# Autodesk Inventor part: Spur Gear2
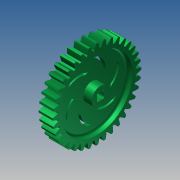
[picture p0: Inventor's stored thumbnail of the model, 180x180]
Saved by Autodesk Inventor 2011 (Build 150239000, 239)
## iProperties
Created: 2010-06
Part Number: Spur Gear2
Material: Steel
Document SubType Name: Modeling
Designer: Phil
Categories: <?xml version="1.0" encoding="UTF-16"?> <MemberInstance><Categories><FamilyTemplate><FamilyTemplateParameter ValueType="xs:double" Id="1" ObjectReferenceKey="da
Density: 1 g/cm^3
CustomPartVersion: 1
Author: Phil
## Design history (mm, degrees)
sketch "Sketch1"
  geometry: C1 r 19.897 at (0, 0)
  constraints: 1 centre point
  dimensions: "d0" = 39.79333 diameter of C1 (= da_da)
extrude "Extrusion1" new body sketch "Sketch1" distance "d1" = 6.35 (= da_b); taper "d2" = 0 deg
sketch "Sketch2"
  geometry: C1 r 19.897 at (0, 0) reference; C2 r 19.05 at (0, 0)
  constraints: 1 centre point, 1 coincident
  dimensions: "d3" = 38.1 diameter of C2 (= da_dw)
feature "Pitch Diameter" sketch "Sketch2" dims "d4" = 76.2, "d5" = 0
workplane "Work Plane1"
workplane "Work Plane2"
workplane "Work Plane3"
feature "Spur Gear" dims "da_b" = 6.35, "da_d" = 38.1, "da_aw" = 25.4, "da_da" = 39.79333, "da_df" = 35.03083, "da_dw" = 38.1, angle "da_beta" = 0 deg, "da_lefttooth" = 0, "da_righttooth" = 0
sketch "Sketch3"
  geometry: C1 r 15.926 at (0, 0); A1 r 19.897 centre (0, 0) between (-3.027, 19.665) and (-3.882, 19.514) reference
  constraints: 1 centre point, 1 coincident
  dimensions: "d20" = 31.8516 diameter of C1
extrude "Extrusion2" cut sketch "Sketch3" distance "d21" = 2.1844; taper "d22" = 0 deg
fillet "Fillet1" dims "d23" = 0.9906
workplane "Work Plane4"
mirror "Mirror1"
sketch "Sketch4"
  geometry: A1 r 8.483 centre (0, 0) between (6.167, 5.824) and (5.124, 6.76); A2 r 8.483 centre (0, 0) between (8.127, -2.429) and (8.416, -1.058); A3 r 12.767 centre (0, 0) between (12.018, 4.309) and (11.316, 5.912); A4 r 8.483 centre (0, 0) between (1.96, -8.253) and (3.292, -7.818); A5 r 12.767 centre (0, 0) between (9.741, -8.254) and (10.778, -6.845); A6 r 12.767 centre (0, 0) between (2.278, 12.563) and (0.539, 12.756); A7 r 8.483 centre (0, 0) between (-1.96, 8.253) and (-3.292, 7.818); A8 r 12.767 centre (0, 0) between (-9.741, 8.254) and (-10.778, 6.845); A9 r 8.483 centre (0, 0) between (-8.127, 2.429) and (-8.416, 1.058); A10 r 8.483 centre (0, 0) between (-6.167, -5.824) and (-5.124, -6.76); A11 r 12.767 centre (0, 0) between (-12.018, -4.309) and (-11.316, -5.912); A12 r 12.767 centre (0, 0) between (-2.278, -12.563) and (-0.539, -12.756)
  constraints: 24 point on circle, 12 centre point, 24 other
extrude "Extrusion3" cut sketch "Sketch4" stored distance "d24" = 2.5781; taper "d25" = 0 deg
sketch "Sketch5"
  geometry: C1 r 14.935 at (0, 0) reference; C2 r 4.001 at (0, 0)
  constraints: 1 centre point, 1 coincident
  dimensions: "d26" = 8.001 diameter of C2
extrude "Extrusion4" join sketch "Sketch5" distance "d27" = 3.7592; taper "d28" = 0 deg
mirror "Mirror2"
sketch "Sketch6"
  geometry: L1 (1.612, 0.952)-(1.558, 1.007); L2 (1.558, 1.025)-(1.612, 1.079); L3 (1.612, 1.104)-(1.612, 1.079); L4 (1.558, 1.177)-(1.612, 1.231); L5 (1.612, 1.362)-(1.612, 1.231); L6 (1.232, 1.612)-(1.177, 1.558); L7 (1.159, 1.558)-(1.105, 1.612); L8 (1.079, 1.612)-(1.105, 1.612); L9 (1.232, 1.612)-(1.362, 1.612); L10 (1.612, 0.952)-(1.612, -0.952); L11 (1.558, -1.007)-(1.612, -0.952); L12 (1.612, 1.104)-(1.558, 1.159); L13 (1.079, 1.612)-(1.025, 1.558); L14 (-1.362, 1.612)-(-1.231, 1.612); L15 (-1.177, 1.558)-(-1.231, 1.612); L16 (1.007, 1.558)-(0.952, 1.612); L17 (-0.952, 1.613)-(0.952, 1.612); L18 (-0.952, 1.613)-(-1.007, 1.558); L19 (-1.024, 1.558)-(-1.079, 1.612); L20 (-1.104, 1.613)-(-1.079, 1.612); L21 (-1.104, 1.613)-(-1.159, 1.558); L22 (1.613, -1.079)-(1.558, -1.024); L23 (1.613, -1.079)-(1.612, -1.105); L24 (1.558, -1.159)-(1.612, -1.105); L25 (1.613, -1.231)-(1.558, -1.177); L26 (1.613, -1.231)-(1.612, -1.362); L27 (1.362, -1.612)-(1.231, -1.612); L28 (1.177, -1.558)-(1.231, -1.612); L29 (1.104, -1.613)-(1.079, -1.612); L30 (1.024, -1.558)-(1.079, -1.612); L31 (0.952, -1.613)-(1.007, -1.558); L32 (0.952, -1.613)-(-0.952, -1.612); L33 (1.104, -1.613)-(1.159, -1.558); L34 (-1.007, -1.558)-(-0.952, -1.612); L35 (-1.079, -1.612)-(-1.025, -1.558); L36 (-1.079, -1.612)-(-1.105, -1.612); L37 (-1.159, -1.558)-(-1.105, -1.612); L38 (-1.232, -1.612)-(-1.177, -1.558); L39 (-1.612, -0.952)-(-1.558, -1.007); L40 (-1.558, -1.025)-(-1.612, -1.079); L41 (-1.612, -1.104)-(-1.612, -1.079); L42 (-1.612, -1.104)-(-1.558, -1.159); L43 (-1.558, -1.177)-(-1.612, -1.231); L44 (-1.612, -1.362)-(-1.612, -1.231); L45 (-1.232, -1.612)-(-1.362, -1.612); L46 (-1.612, -0.952)-(-1.612, 0.952); L47 (-1.558, 1.007)-(-1.612, 0.952); L48 (-1.613, 1.079)-(-1.558, 1.024); L49 (-1.613, 1.079)-(-1.612, 1.105); L50 (-1.558, 1.159)-(-1.612, 1.105); L51 (-1.613, 1.231)-(-1.558, 1.177); L52 (-1.613, 1.231)-(-1.612, 1.362); A1 r 0.013 centre (1.567, 1.016) between (1.558, 1.025) and (1.558, 1.007); A2 r 0.013 centre (1.567, 1.168) between (1.558, 1.177) and (1.558, 1.159); A3 r 0.25 centre (1.362, 1.362) between (1.612, 1.362) and (1.362, 1.612); A4 r 0.013 centre (1.168, 1.567) between (1.159, 1.558) and (1.177, 1.558); A5 r 0.012 centre (-1.016, 1.566) between (-1.024, 1.558) and (-1.007, 1.558); A6 r 0.012 centre (-1.168, 1.566) between (-1.177, 1.558) and (-1.159, 1.558); A7 r 0.013 centre (1.016, 1.567) between (1.007, 1.558) and (1.025, 1.558); A8 r 0.012 centre (1.566, -1.016) between (1.558, -1.007) and (1.558, -1.024); A9 r 0.013 centre (1.567, -1.168) between (1.558, -1.159) and (1.558, -1.177); A10 r 0.25 centre (1.362, -1.362) between (1.362, -1.612) and (1.612, -1.362); A11 r 0.012 centre (1.168, -1.566) between (1.177, -1.558) and (1.159, -1.558); A12 r 0.012 centre (1.016, -1.566) between (1.024, -1.558) and (1.007, -1.558); A13 r 0.013 centre (-1.016, -1.567) between (-1.007, -1.558) and (-1.025, -1.558); A14 r 0.013 centre (-1.168, -1.567) between (-1.159, -1.558) and (-1.177, -1.558); A15 r 0.013 centre (-1.567, -1.168) between (-1.558, -1.177) and (-1.558, -1.159); A16 r 0.013 centre (-1.567, -1.016) between (-1.558, -1.025) and (-1.558, -1.007); A17 r 0.25 centre (-1.362, -1.362) between (-1.612, -1.362) and (-1.362, -1.612); A18 r 0.25 centre (-1.362, 1.362) between (-1.362, 1.612) and (-1.612, 1.362); A19 r 0.013 centre (-1.567, 1.168) between (-1.558, 1.159) and (-1.558, 1.177); A20 r 0.012 centre (-1.566, 1.016) between (-1.558, 1.007) and (-1.558, 1.024); 1 further point
  constraints: 104 end point, 40 point on circle, 20 centre point
feature "iFeature2:1" sketch "Sketch6"
body "Solid1"
body "Srf1"
other parameters: "d6" = 0, "d7" = 5 deg (computed from da_z), "d9" = 0, "d14" = 0, "d15" = 25.4 (= da_aw), "d16" = 0, "d17" = 0, "d18" = 0, "d19" = 25.4 (= da_aw)
